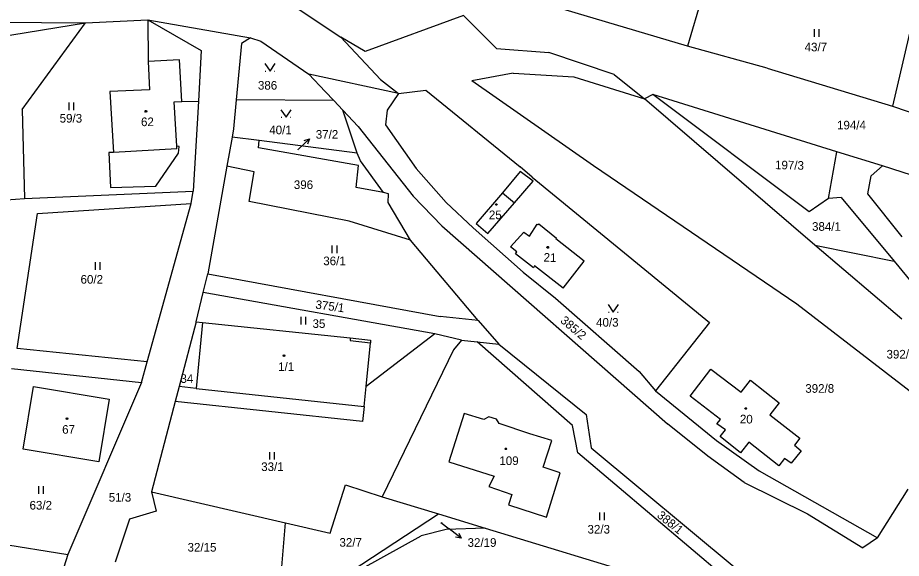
# Model space of a CAD drawing. Extents: x -811039 to -805820, y -1161436 to -1155864.
# Drawn here: x -806560.9 to -806387, y -1158088 to -1157981.5 of the extents above; entities that cross this region are included whole.
import ezdxf

# ---------------------------------------------------------------- set-up
doc = ezdxf.new("R2010")
doc.units = 0
for name, color, linetype in [('Default', 7, 'Continuous'), ('KN_HRANICE', 7, 'Continuous'), ('KN_KULTURY', 7, 'Continuous'), ('KN_PARCELY', 7, 'Continuous'), ('KN_SLUCKY', 7, 'Continuous')]:
    doc.layers.add(name, color=color, linetype=linetype)

# ---------------------------------------------------------------- blocks, each defined once
blk = doc.blocks.new('306')
at = {"layer": 'Default'}
for p, q in [((-0.5, 1.5), (-0.5, 0)), ((0.5, 0), (0.5, 1.5))]:
    blk.add_line(p, q, dxfattribs=at)
blk = doc.blocks.new('314')
at = {"layer": 'Default'}
for p, q in [((-0.95, 0), (-0.85, 0)), ((0.85, 0), (0.95, 0))]:
    blk.add_line(p, q, dxfattribs=at)
blk.add_lwpolyline([(-1, 1.5), (0, 0), (1, 1.5)], dxfattribs=at)
blk = doc.blocks.new('10292')
at = {"layer": 'Default'}
blk.add_line((0, 3), (0, 0), dxfattribs=at)
blk.add_lwpolyline([(-0.5, 2), (0, 3), (0.5, 2)], dxfattribs=at)
blk = doc.blocks.new('402')
at = {"layer": 'Default'}
blk.add_lwpolyline([(0.09, 0.15), (0.18, 0), (0.09, -0.15), (-0.09, -0.15), (-0.18, 0), (-0.09, 0.15), (0.09, 0.15)], dxfattribs=at)

msp = doc.modelspace()

# ---------------------------------------------------------------- linework, layer by layer
at = {"layer": 'KN_HRANICE'}
for p, q in [((-806515.35, -1157973.25), (-806497.28, -1157985.34)), ((-806424.9, -1157973.07), (-806429.06, -1157987.06)), ((-806383.1, -1157974.77), (-806388.68, -1157998.88)), ((-806429.06, -1157987.06), (-806462.21, -1157977.22)), ((-806547.55, -1157982.51), (-806535.26, -1157981.87)), ((-806535.26, -1157981.87), (-806524.76, -1157987.91)), ((-806535.26, -1157981.87), (-806535.24, -1157990.09)), ((-806535.26, -1157981.87), (-806515.08, -1157985.46)), ((-806473.17, -1157981.08), (-806492.48, -1157988.16)), ((-806473.17, -1157981.08), (-806466.66, -1157987.53)), ((-806593.91, -1157982.13), (-806547.55, -1157982.51)), ((-806570.5, -1157986.22), (-806547.55, -1157982.51)), ((-806559.98, -1157999.53), (-806547.55, -1157982.51)), ((-806497.28, -1157985.34), (-806489.51, -1157993.66)), ((-806492.48, -1157988.16), (-806497.28, -1157985.34)), ((-806516.85, -1157986.57), (-806517.87, -1157997.67)), ((-806515.08, -1157985.46), (-806516.85, -1157986.57)), ((-806515.08, -1157985.46), (-806513.04, -1157986.1)), ((-806513.04, -1157986.1), (-806503.58, -1157992.63)), ((-806413.41, -1157991.42), (-806429.06, -1157987.06)), ((-806524.76, -1157987.91), (-806525.33, -1157997.9)), ((-806466.66, -1157987.53), (-806456.36, -1157988.35)), ((-806443.47, -1157992.64), (-806456.36, -1157988.35)), ((-806535.24, -1157990.09), (-806534.96, -1157995.68)), ((-806463.35, -1157992.4), (-806471.54, -1157993.92)), ((-806463.35, -1157992.4), (-806451.44, -1157993.16)), ((-806413.41, -1157991.42), (-806388.68, -1157998.88)), ((-806503.58, -1157992.63), (-806500.35, -1157996.02)), ((-806485.92, -1157996.44), (-806503.58, -1157992.63)), ((-806489.51, -1157993.66), (-806485.92, -1157996.44)), ((-806447.58, -1158010.64), (-806471.54, -1157993.92)), ((-806451.44, -1157993.16), (-806437.53, -1157997.48)), ((-806443.47, -1157992.64), (-806437.53, -1157997.48)), ((-806534.96, -1157995.68), (-806542.76, -1157995.99)), ((-806485.92, -1157996.44), (-806480.54, -1157995.78)), ((-806480.54, -1157995.78), (-806462.02, -1158010.88)), ((-806542.76, -1157995.99), (-806542.05, -1158008)), ((-806498.69, -1157997.8), (-806500.35, -1157996.02)), ((-806485.92, -1157996.44), (-806488.17, -1157999.72)), ((-806435.86, -1157996.63), (-806437.53, -1157997.48)), ((-806403.97, -1158026.28), (-806437.53, -1157997.48)), ((-806399.64, -1158007.89), (-806435.86, -1157996.63)), ((-806405.11, -1158019.7), (-806435.86, -1157996.63)), ((-806530.07, -1157998.08), (-806528.61, -1157998)), ((-806529.55, -1158006.81), (-806530.07, -1157998.08)), ((-806528.61, -1157998), (-806525.33, -1157997.9)), ((-806525.33, -1157997.9), (-806526.35, -1158015.67)), ((-806517.87, -1157997.67), (-806518.4, -1158003.39)), ((-806498.69, -1157997.8), (-806517.87, -1157997.67)), ((-806496.9, -1157999.7), (-806498.69, -1157997.8)), ((-806388.68, -1157998.88), (-806381.62, -1158001.34)), ((-806559.98, -1157999.53), (-806559.56, -1158017.1)), ((-806493.88, -1158002.92), (-806496.9, -1157999.7)), ((-806494.05, -1158008.15), (-806496.9, -1157999.7)), ((-806488.17, -1157999.72), (-806488.47, -1158002.57)), ((-806488.47, -1158002.57), (-806482.44, -1158011.2)), ((-806518.4, -1158003.39), (-806518.69, -1158005.01)), ((-806493.88, -1158002.92), (-806483.05, -1158016.65)), ((-806518.69, -1158005.01), (-806519.71, -1158010.72)), ((-806513.35, -1158005.69), (-806518.69, -1158005.01)), ((-806513.52, -1158007.08), (-806513.35, -1158005.69)), ((-806494.05, -1158008.15), (-806513.35, -1158005.69)), ((-806542.05, -1158008), (-806542.93, -1158008.02)), ((-806542.93, -1158008.02), (-806542.62, -1158014.9)), ((-806529.1, -1158006.88), (-806529.55, -1158006.81)), ((-806529.21, -1158008.16), (-806529.1, -1158006.88)), ((-806493.83, -1158010.58), (-806513.52, -1158007.08)), ((-806401.34, -1158017.08), (-806399.64, -1158007.89)), ((-806390.69, -1158010.65), (-806399.64, -1158007.89)), ((-806533.68, -1158014.66), (-806529.21, -1158008.16)), ((-806493.41, -1158009.65), (-806494.05, -1158008.15)), ((-806488.91, -1158015.93), (-806493.41, -1158009.65)), ((-806519.71, -1158010.72), (-806523.5, -1158031.94)), ((-806514.38, -1158011.87), (-806519.71, -1158010.72)), ((-806494.26, -1158014.93), (-806493.83, -1158010.58)), ((-806482.44, -1158011.2), (-806476.53, -1158017.89)), ((-806459.64, -1158012.89), (-806462.02, -1158010.88)), ((-806407.54, -1158037.9), (-806447.58, -1158010.64)), ((-806392.94, -1158012.61), (-806390.69, -1158010.65)), ((-806376.12, -1158015.37), (-806390.69, -1158010.65)), ((-806515.31, -1158017.65), (-806514.38, -1158011.87)), ((-806462.01, -1158011.79), (-806465.47, -1158015.95)), ((-806459.45, -1158013.66), (-806462.01, -1158011.79)), ((-806459.64, -1158012.89), (-806424.73, -1158041.5)), ((-806393.59, -1158016.18), (-806392.94, -1158012.61)), ((-806542.62, -1158014.9), (-806533.68, -1158014.66)), ((-806488.91, -1158015.93), (-806494.26, -1158014.93)), ((-806463.14, -1158017.92), (-806459.45, -1158013.66)), ((-806559.56, -1158017.1), (-806526.35, -1158015.67)), ((-806526.74, -1158018.07), (-806526.35, -1158015.67)), ((-806487.91, -1158016.15), (-806488.91, -1158015.93)), ((-806487.98, -1158017.86), (-806487.91, -1158016.15)), ((-806483.05, -1158016.65), (-806477.41, -1158022.47)), ((-806465.47, -1158015.95), (-806470.67, -1158022.04)), ((-806386.8, -1158024.62), (-806393.59, -1158016.18)), ((-806600.28, -1158020.19), (-806559.56, -1158017.1)), ((-806556.99, -1158020.02), (-806526.74, -1158018.07)), ((-806535.38, -1158049.27), (-806526.74, -1158018.07)), ((-806495.62, -1158021.57), (-806515.31, -1158017.65)), ((-806483.56, -1158025.28), (-806487.98, -1158017.86)), ((-806476.53, -1158017.89), (-806471.26, -1158022.84)), ((-806468.38, -1158024.01), (-806463.14, -1158017.92)), ((-806401.34, -1158017.08), (-806405.11, -1158019.7)), ((-806398.79, -1158016.9), (-806401.34, -1158017.08)), ((-806398.79, -1158016.9), (-806388.41, -1158029.46)), ((-806561.02, -1158046.66), (-806556.99, -1158020.02)), ((-806483.56, -1158025.28), (-806495.62, -1158021.57)), ((-806477.41, -1158022.47), (-806433.02, -1158061.49)), ((-806471.26, -1158022.84), (-806461.38, -1158031.57)), ((-806470.67, -1158022.04), (-806468.38, -1158024.01)), ((-806460.18, -1158024.48), (-806458.64, -1158022.17)), ((-806458.64, -1158022.17), (-806458.51, -1158022.27)), ((-806458.51, -1158022.27), (-806458.31, -1158022.07)), ((-806458.31, -1158022.07), (-806454.85, -1158024.87)), ((-806470.28, -1158041.14), (-806483.56, -1158025.28)), ((-806463.9, -1158026.64), (-806461.29, -1158023.72)), ((-806461.29, -1158023.72), (-806460.18, -1158024.48)), ((-806454.85, -1158024.87), (-806454.96, -1158025.05)), ((-806449.4, -1158029.4), (-806454.96, -1158025.05)), ((-806462.62, -1158027.62), (-806463.9, -1158026.64)), ((-806386.86, -1158040.87), (-806403.97, -1158026.28)), ((-806403.97, -1158026.28), (-806388.41, -1158029.46)), ((-806462.9, -1158027.97), (-806462.62, -1158027.62)), ((-806459.38, -1158030.74), (-806462.9, -1158027.97)), ((-806459.17, -1158030.38), (-806459.38, -1158030.74)), ((-806453.55, -1158034.74), (-806459.17, -1158030.38)), ((-806453.55, -1158034.74), (-806449.4, -1158029.4)), ((-806388.41, -1158029.46), (-806380.92, -1158038.53)), ((-806524.37, -1158035.58), (-806523.5, -1158031.94)), ((-806523.5, -1158031.94), (-806477.72, -1158040.31)), ((-806461.38, -1158031.57), (-806455.07, -1158036.74)), ((-806525.75, -1158041.38), (-806524.37, -1158035.58)), ((-806478.78, -1158043.77), (-806524.37, -1158035.58)), ((-806455.07, -1158036.74), (-806438.57, -1158051.14)), ((-806365.29, -1158070.57), (-806407.54, -1158037.9)), ((-806470.28, -1158041.14), (-806477.72, -1158040.31)), ((-806525.75, -1158041.38), (-806529.12, -1158054.14)), ((-806524.55, -1158041.53), (-806525.79, -1158054.5)), ((-806525.75, -1158041.38), (-806524.55, -1158041.53)), ((-806524.55, -1158041.53), (-806495.43, -1158044.56)), ((-806470.28, -1158041.14), (-806466.19, -1158045.76)), ((-806424.73, -1158041.5), (-806435.36, -1158054.95)), ((-806495.43, -1158044.56), (-806491.42, -1158044.98)), ((-806478.78, -1158043.77), (-806492.33, -1158054.1)), ((-806473.53, -1158044.96), (-806478.78, -1158043.77)), ((-806492.33, -1158054.1), (-806491.47, -1158045.52)), ((-806491.42, -1158044.98), (-806491.47, -1158045.52)), ((-806473.53, -1158044.96), (-806475.11, -1158046.92)), ((-806473.53, -1158044.96), (-806470.44, -1158045.3)), ((-806470.44, -1158045.3), (-806466.19, -1158045.76)), ((-806451.67, -1158061.82), (-806470.44, -1158045.3)), ((-806466.19, -1158045.76), (-806449.03, -1158059.61)), ((-806535.38, -1158049.27), (-806561.02, -1158046.66)), ((-806475.11, -1158046.92), (-806489.16, -1158075.84)), ((-806536.5, -1158053.32), (-806535.38, -1158049.27)), ((-806562.08, -1158050.54), (-806536.5, -1158053.32)), ((-806438.57, -1158051.14), (-806435.36, -1158054.95)), ((-806428.54, -1158056.05), (-806424.44, -1158050.68)), ((-806424.44, -1158050.68), (-806418.49, -1158055.25)), ((-806418.49, -1158055.25), (-806416.65, -1158052.89)), ((-806416.65, -1158052.89), (-806411, -1158057.31)), ((-806559.82, -1158066.44), (-806557.77, -1158054.14)), ((-806557.77, -1158054.14), (-806542.9, -1158056.58)), ((-806536.5, -1158053.32), (-806551.02, -1158087.22)), ((-806529.12, -1158054.14), (-806529.89, -1158057.08)), ((-806525.79, -1158054.5), (-806529.12, -1158054.14)), ((-806492.73, -1158058.03), (-806492.33, -1158054.1)), ((-806435.36, -1158054.95), (-806423.34, -1158064.76)), ((-806542.9, -1158056.58), (-806544.93, -1158068.95)), ((-806422.57, -1158060.63), (-806428.54, -1158056.05)), ((-806529.89, -1158057.08), (-806534.57, -1158074.85)), ((-806493.03, -1158061.03), (-806529.89, -1158057.08)), ((-806492.73, -1158058.03), (-806493.03, -1158061.03)), ((-806411, -1158057.31), (-806412.87, -1158059.71)), ((-806473, -1158059.4), (-806476.02, -1158068.96)), ((-806469.12, -1158060.6), (-806473, -1158059.4)), ((-806468.17, -1158060.1), (-806469.12, -1158060.6)), ((-806466.63, -1158060.55), (-806468.17, -1158060.1)), ((-806449.03, -1158059.61), (-806448.04, -1158066.18)), ((-806412.87, -1158059.71), (-806406.95, -1158064.32)), ((-806466.1, -1158061.37), (-806466.63, -1158060.55)), ((-806460.11, -1158063.43), (-806466.1, -1158061.37)), ((-806450.67, -1158067.18), (-806451.67, -1158061.82)), ((-806425.05, -1158067.84), (-806433.02, -1158061.49)), ((-806423.26, -1158061.45), (-806422.57, -1158060.63)), ((-806421.58, -1158062.68), (-806423.26, -1158061.45)), ((-806455.77, -1158064.77), (-806460.11, -1158063.43)), ((-806422.65, -1158063.96), (-806421.58, -1158062.68)), ((-806457.45, -1158070.02), (-806455.77, -1158064.77)), ((-806423.34, -1158064.76), (-806414.94, -1158070.73)), ((-806418.65, -1158067.15), (-806422.65, -1158063.96)), ((-806416.97, -1158065.05), (-806418.65, -1158067.15)), ((-806411.06, -1158069.72), (-806416.97, -1158065.05)), ((-806406.95, -1158064.32), (-806408.03, -1158065.7)), ((-806544.93, -1158068.95), (-806559.82, -1158066.44)), ((-806421.5, -1158091.87), (-806450.67, -1158067.18)), ((-806448.04, -1158066.18), (-806419.5, -1158089.94)), ((-806406.7, -1158066.76), (-806408.66, -1158069.24)), ((-806408.03, -1158065.7), (-806406.7, -1158066.76)), ((-806417.91, -1158073.02), (-806425.05, -1158067.84)), ((-806409.96, -1158068.27), (-806411.06, -1158069.72)), ((-806408.66, -1158069.24), (-806409.96, -1158068.27)), ((-806476.02, -1158068.96), (-806467.11, -1158071.76)), ((-806454.13, -1158071.1), (-806457.45, -1158070.02)), ((-806467.11, -1158071.76), (-806468.17, -1158073.81)), ((-806456.84, -1158079.87), (-806454.13, -1158071.1)), ((-806414.94, -1158070.73), (-806391.65, -1158083.89)), ((-806499.42, -1158082.98), (-806496.39, -1158073.48)), ((-806496.39, -1158073.48), (-806489.16, -1158075.84)), ((-806468.17, -1158073.81), (-806463.61, -1158075.41)), ((-806417.91, -1158073.02), (-806405.43, -1158079.22)), ((-806534.57, -1158074.85), (-806533.65, -1158078.66)), ((-806534.57, -1158074.85), (-806508.21, -1158080.94)), ((-806489.16, -1158075.84), (-806478.06, -1158079.22)), ((-806463.61, -1158075.41), (-806464.26, -1158077.39)), ((-806391.65, -1158083.89), (-806385.61, -1158074.34)), ((-806464.26, -1158077.39), (-806456.84, -1158079.87)), ((-806533.65, -1158078.66), (-806538.91, -1158080.23)), ((-806502.01, -1158094.85), (-806478.06, -1158079.22)), ((-806478.06, -1158079.22), (-806468.91, -1158082)), ((-806405.43, -1158079.22), (-806394.55, -1158085.89)), ((-806538.91, -1158080.23), (-806541.73, -1158088.69)), ((-806509.31, -1158095.01), (-806508.21, -1158080.94)), ((-806508.21, -1158080.94), (-806499.42, -1158082.98)), ((-806476.57, -1158082.28), (-806481.45, -1158083.51)), ((-806468.91, -1158082), (-806476.57, -1158082.28)), ((-806468.91, -1158082), (-806424.62, -1158095.47)), ((-806502.01, -1158094.85), (-806481.45, -1158083.51)), ((-806391.65, -1158083.89), (-806394.55, -1158085.89)), ((-806566.96, -1158084.66), (-806551.02, -1158087.22)), ((-806551.02, -1158087.22), (-806553.63, -1158095.33))]:
    msp.add_line(p, q, dxfattribs=at)
at = {"layer": 'KN_PARCELY'}
for p, q in [((-806505.72, -1158007.51), (-806505.61, -1158007.4)), ((-806477.62, -1158080.92), (-806475.98, -1158082.17))]:
    msp.add_line(p, q, dxfattribs=at)
at = {"layer": 'KN_SLUCKY'}
for p, q in [((-806529.04, -1157989.75), (-806535.24, -1157990.09)), ((-806528.61, -1157998), (-806529.04, -1157989.75)), ((-806529.55, -1158007.3), (-806542.05, -1158008)), ((-806529.55, -1158007.3), (-806529.55, -1158006.81)), ((-806465.47, -1158015.95), (-806463.14, -1158017.92)), ((-806495.43, -1158044.56), (-806495.48, -1158045.06)), ((-806495.48, -1158045.06), (-806491.47, -1158045.52)), ((-806525.79, -1158054.5), (-806492.73, -1158058.03))]:
    msp.add_line(p, q, dxfattribs=at)

# ---------------------------------------------------------------- block references
at = {"layer": 'KN_KULTURY'}
for name, p in [('306', (-806403.65, -1157985.22)), ('314', (-806511.22, -1157991.99)), ('306', (-806550.34, -1157999.7)), ('402', (-806535.66, -1157999.91)), ('314', (-806508.07, -1158001.1)), ('402', (-806466.67, -1158018.26)), ('306', (-806498.54, -1158027.84)), ('402', (-806456.56, -1158026.7)), ('306', (-806545.16, -1158031.16)), ('314', (-806443.66, -1158039.45)), ('306', (-806504.66, -1158041.91)), ('402', (-806508.46, -1158048.03)), ('402', (-806417.59, -1158058.46)), ('402', (-806551.2, -1158060.45)), ('306', (-806510.86, -1158068.52)), ('402', (-806464.81, -1158066.4)), ('306', (-806556.32, -1158075.27)), ('306', (-806445.87, -1158080.46))]:
    msp.add_blockref(name, p, dxfattribs=at)
at = {"layer": 'KN_PARCELY'}
for p, rotation in [((-806505.61, -1158007.4), -45.789945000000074), ((-806475.98, -1158082.17), -127.32183900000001)]:
    msp.add_blockref('10292', p, dxfattribs=dict(at, rotation=rotation))

# ---------------------------------------------------------------- texts
for s, height, p in [('43/7', 1.7, (-806406.01, -1157988.11)), ('386', 1.7, (-806513.61, -1157995.65)), ('59/3', 1.7, (-806552.63, -1158002.14)), ('62', 1.7, (-806536.62, -1158002.84)), ('40/1', 1.7, (-806511.38, -1158004.44)), ('194/4', 1.7, (-806399.63, -1158003.48)), ('37/2', 1.7, (-806502.22, -1158005.31)), ('37/2', 0.1, (-806505.92, -1158007.51)), ('396', 1.7, (-806506.54, -1158015.22)), ('25', 1.7, (-806468.15, -1158021.16)), ('384/1', 1.7, (-806404.55, -1158023.45)), ('36/1', 1.7, (-806500.75, -1158030.23)), ('60/2', 1.7, (-806548.52, -1158033.86)), ('35', 1.7, (-806502.86, -1158042.58)), ('40/3', 1.7, (-806447.05, -1158042.33)), ('392/7', 1.7, (-806389.89, -1158048.61)), ('1/1', 1.7, (-806509.63, -1158051.06)), ('34', 1.7, (-806528.86, -1158053.41)), ('392/8', 1.7, (-806405.88, -1158055.35)), ('67', 1.7, (-806552.14, -1158063.42)), ('109', 1.7, (-806466.09, -1158069.58)), ('33/1', 1.7, (-806512.96, -1158070.76)), ('51/3', 1.7, (-806542.97, -1158076.79)), ('63/2', 1.7, (-806558.56, -1158078.35)), ('32/19', 0.1, (-806477.61, -1158080.92)), ('32/3', 1.7, (-806448.74, -1158083.08)), ('32/7', 1.7, (-806497.56, -1158085.66)), ('32/19', 1.7, (-806472.35, -1158085.69)), ('32/15', 1.7, (-806527.46, -1158086.63))]:
    msp.add_text(s, height=height, dxfattribs=at).set_placement(p)
for s, rotation, p in [('197/3', 358.614, (-806411.85, -1158011.3)), ('21', 357.755, (-806457.41, -1158029.51)), ('375/1', 352.541, (-806502.36, -1158038.77)), ('385/2', 319.424, (-806454.22, -1158041.34)), ('20', 358.786, (-806418.77, -1158061.36)), ('388/1', 321.028, (-806435.19, -1158079.75))]:
    msp.add_text(s, height=1.7, rotation=rotation, dxfattribs=at).set_placement(p)

doc.saveas('drawing.dxf')
